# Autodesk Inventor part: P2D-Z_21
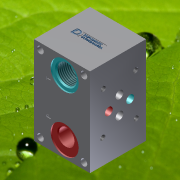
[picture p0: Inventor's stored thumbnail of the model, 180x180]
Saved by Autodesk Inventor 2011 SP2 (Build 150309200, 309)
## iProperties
Category: PARTsolutions
Company: DUPLOMATIC
Created: 2013-08
Part Number: P2D-Z_21
Catalog Web Link: www.cadenas.de
Description: P2D-*-Modular subplates
Vendor: DUPLOMATIC
Document SubType Name: Modeling
Designer: PARTuser1
Manufacturer: DUPLOMATIC
Density: 1 g/cm^3
PSOL_IDENT_0: {$CADENAS_DATA\23d-libs\duplomatic\05_subplates_and_manifolds\52000\p2d.prj},165 {VTYP=3D},{NB=15600
PSOL_IDENT_1: 25-06},{LINA=P2D-Z/21},{NN=P2D-*},{DATE=08.11.2012 07:04:15},{GEOMDATE=07.11.2012 00:00:00},{VERSION
PSOL_IDENT_2: =},{LINEID=10},{LINESUBID=-1},{WBVAR=VER,GU}  {NB=1560025-06},{LINA=P2D-Z/21},{KT=DUMMY},{CODE=15600
PSOL_IDENT_3: 25-06},{TIPO=P2D},{VER=Z},{SER=21},{GU=},{PORT=Rear ports},{LAG=P2D-Z/21},{VERS=4}
CNS_NT: Modular subplates
CNS_NB: 1560025-06
CNS_NBSYN: $CODE.$GU.
CNS_LINA: P2D-Z/21
CNS_CODE: 1560025-06
CNS_TIPO: P2D
CNS_VER: Z = arranged for the installation of an MZD
CNS_SER: 21
CNS_GU: NBR
CNS_PORT: Rear ports
CNS_LAG: P2D-Z/21
CNS_VERS: 4
SUPPLIER: DUPLOMATIC
ARTICLENO: 1560025-06
BOMINFO: P2D-Z/21
CREATOR: CADENAS GmbH
Title: P2D-Z/21
Author: Cadenas PARTsolutions
Comments: Modular subplates
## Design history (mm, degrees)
sketch "Sketch_1"
  geometry: L1 (-27, 27)-(-27, -27); L2 (-27, -27)-(27, -27); L3 (27, -27)-(27, 27); L4 (27, 27)-(-27, 27)
  constraints: 8 end point
extrude "Extrusion1" join sketch "Sketch_1" stored distance "d0" = 85; taper "d1" = 0 deg
sketch "Sketch_2"
  geometry: L1 (-27, -8)-(-27, -27); L2 (-27, -27)-(-40.5, -27); L3 (-40.5, -27)-(-40.5, -25.7); L4 (-40.5, -25.7)-(-37.477, -25.7); L5 (-37.477, -25.7)-(-36.316, -24.538); L6 (-36.316, -24.538)-(-36.316, -8); L7 (-36.316, -8)-(-27, -8); L8 (-27, -8)-(-27, -27)
  constraints: 16 end point
revolve "Revolution1" sketch "Sketch_2" stored, may be unused: angle "d2" = 360 deg
thread "Thread1" dims "d3" = 14.5, "d4" = 3.2
sketch "Sketch3"
  geometry: 1 further point
hole "Drilling 2" sketch "Sketch3" at (29.5, 17.5) diameter "d5" = 14.95; stored, may be unused: countersink angle "d9" = 90 deg, drill point angle "d11" = 0 deg; dims "d6" = 6, "d7" = 16.662, "d8" = 2, "d10" = 35
sketch "Sketch_30"
  geometry: L1 (27, -25.7)-(27, -27); L2 (27, -27)-(13.5, -27); L3 (13.5, -27)-(13.5, -25.7); L4 (13.5, -25.7)-(27, -25.7); L5 (27, -25.7)-(27, -27)
  constraints: 10 end point
revolve "Revolution2" sketch "Sketch_30" stored, may be unused: angle "d12" = 360 deg
sketch "Sketch5"
  geometry: 1 further point
hole "Drilling 4" sketch "Sketch5" at (0, 2) diameter "d13" = 14.95; stored, may be unused: countersink angle "d17" = 90 deg, drill point angle "d19" = 120 deg; dims "d14" = 6, "d15" = 16.662, "d16" = 2, "d18" = 17.88431
sketch "Sketch6"
  geometry: 1 further point
hole "Drilling 5" sketch "Sketch6" at (29.5, 67.5) diameter "d20" = 14.95; stored, may be unused: countersink angle "d24" = 90 deg, drill point angle "d26" = 120 deg; dims "d21" = 6, "d22" = 16.662, "d23" = 2, "d25" = 22.68431
sketch "Sketch7"
  geometry: 1 further point
hole "Drilling 6" sketch "Sketch7" at (6, -6) diameter "d27" = 6.3; stored, may be unused: countersink angle "d31" = 90 deg, drill point angle "d33" = 0 deg; dims "d28" = 6, "d29" = 6.7, "d30" = 2, "d32" = 54
pattern_linear "Rectangular Pattern1" dims "d36" = 42, "d39" = 73
sketch "Sketch8"
  geometry: 1 further point
hole "Drilling 7" sketch "Sketch8" at (42.5, 18.2) diameter "d40" = 7.5; stored, may be unused: countersink angle "d44" = 90 deg, drill point angle "d46" = 120 deg; dims "d41" = 6, "d42" = 4, "d43" = 2, "d45" = 25.83494
sketch "Sketch9"
  geometry: 1 further point
hole "Drilling 8" sketch "Sketch9" at (42.5, 38.8) diameter "d47" = 7.5; stored, may be unused: countersink angle "d51" = 90 deg, drill point angle "d53" = 120 deg; dims "d48" = 6, "d49" = 4, "d50" = 2, "d52" = 25.83494
sketch "Sketch10"
  geometry: 1 further point
hole "Drilling 9" sketch "Sketch10" at (33.7, 28.5) diameter "d54" = 7.5; stored, may be unused: countersink angle "d58" = 90 deg, drill point angle "d60" = 120 deg; dims "d55" = 6, "d56" = 4, "d57" = 2, "d59" = 42.83494
sketch "Sketch11"
  geometry: 1 further point
hole "Drilling 10" sketch "Sketch11" at (51.2, 28.5) diameter "d61" = 7.5; stored, may be unused: countersink angle "d65" = 90 deg, drill point angle "d67" = 120 deg; dims "d62" = 6, "d63" = 4, "d64" = 2, "d66" = 42.83494
sketch "Sketch12"
  geometry: 1 further point
hole "Drilling 11" sketch "Sketch12" at (21, 13.05) diameter "d68" = 4.134; stored, may be unused: countersink angle "d72" = 90 deg, drill point angle "d74" = 120 deg; dims "d69" = 10, "d70" = 5, "d71" = 2, "d73" = 11.80662
sketch "Sketch13"
  geometry: 1 further point
hole "Pattern 2_Drilling 11_3" sketch "Sketch13" at (61.5, 44.8) diameter "d75" = 4.134; stored, may be unused: countersink angle "d79" = 90 deg, drill point angle "d81" = 120 deg; dims "d76" = 10, "d77" = 5, "d78" = 2, "d80" = 11.80662
sketch "Sketch14"
  geometry: 1 further point
hole "Pattern 2_Drilling 11_2" sketch "Sketch14" at (21, 44.05) diameter "d82" = 4.134; stored, may be unused: countersink angle "d86" = 90 deg, drill point angle "d88" = 120 deg; dims "d83" = 10, "d84" = 5, "d85" = 2, "d87" = 11.80662
sketch "Sketch15"
  geometry: 1 further point
hole "Pattern 2_Drilling 11_1" sketch "Sketch15" at (61.5, 12.3) diameter "d89" = 4.134; stored, may be unused: countersink angle "d93" = 90 deg, drill point angle "d95" = 120 deg; dims "d90" = 10, "d91" = 5, "d92" = 2, "d94" = 11.80662
sketch "Sketch_14"
  geometry: L1 (-5.5, -16.5)-(-27, -16.5); L2 (-27, -16.5)-(-27, -4.5); L3 (-27, -4.5)-(-26, -4.5); L4 (-26, -4.5)-(-26, -8.169); L5 (-26, -8.169)-(-25.144, -9.025); L6 (-25.144, -9.025)-(-9.5, -9.025); L7 (-9.5, -9.025)-(-5.5, -16.5); L8 (-5.5, -16.5)-(-27, -16.5)
  constraints: 16 end point
revolve "Revolution3" sketch "Sketch_14" stored, may be unused: angle "d96" = 360 deg
thread "Thread2" dims "d97" = 12.144, "d98" = 0
sketch "Sketch_15"
  geometry: L1 (1.5, 16.5)-(-27, 16.5); L2 (-27, 16.5)-(-27, 28.5); L3 (-27, 28.5)-(-26, 28.5); L4 (-26, 28.5)-(-26, 24.831); L5 (-26, 24.831)-(-25.144, 23.975); L6 (-25.144, 23.975)-(-2.816, 23.975); L7 (-2.816, 23.975)-(1.5, 16.5); L8 (1.5, 16.5)-(-27, 16.5)
  constraints: 16 end point
revolve "Revolution4" sketch "Sketch_15" stored, may be unused: angle "d99" = 360 deg
thread "Thread3" dims "d100" = 12.144, "d101" = 0
sketch "Sketch_16"
  geometry: L1 (-9.422, -3.5)-(12.117, -3.5); L2 (12.117, 3)-(-9.422, 3); L3 (11.496, -2.508)-(11.868, -2.508); L4 (11.868, -2.508)-(12.052, -2.061); L5 (12.052, -2.061)-(12.833, -2.061); L6 (12.833, -2.061)-(13.012, -2.508); L7 (13.012, -2.508)-(13.387, -2.508); L8 (13.387, -2.508)-(12.654, -0.699); L9 (12.654, -0.699)-(12.245, -0.699); L10 (12.245, -0.699)-(11.496, -2.508); L11 (10.766, -2.508)-(11.358, -2.508); L12 (11.358, -2.508)-(11.358, -2.237); L13 (11.358, -2.237)-(10.812, -2.237); L14 (10.794, -0.97)-(11.358, -0.97); L15 (11.358, -0.97)-(11.358, -0.699); L16 (11.358, -0.699)-(10.764, -0.699); L17 (9.283, -0.973)-(9.614, -0.973); L18 (9.614, -0.973)-(9.614, -0.699); L19 (9.614, -0.699)-(9.283, -0.699); L20 (9.283, -0.699)-(9.283, -0.973); L21 (9.283, -2.508)-(9.614, -2.508); L22 (9.614, -2.508)-(9.614, -1.164); L23 (9.614, -1.164)-(9.283, -1.164); L24 (9.283, -1.164)-(9.283, -2.508); L25 (9.507, 0.199)-(10.098, 0.199); L26 (10.098, 0.199)-(10.098, 0.47); L27 (10.098, 0.47)-(9.553, 0.47); L28 (9.534, 1.737)-(10.098, 1.737); L29 (10.098, 1.737)-(10.098, 2.008); L30 (10.098, 2.008)-(9.504, 2.008); L31 (8.023, 0.199)-(8.354, 0.199); L32 (8.354, 0.199)-(8.354, 1.545); L33 (8.354, 1.545)-(8.023, 1.545); L34 (8.023, 1.545)-(8.023, 0.199); L35 (8.023, 1.736)-(8.354, 1.736); L36 (8.354, 1.736)-(8.354, 2.008); L37 (8.354, 2.008)-(8.023, 2.008); L38 (8.023, 2.008)-(8.023, 1.736); L39 (6.885, -2.508)-(7.205, -2.508); L40 (7.205, -2.508)-(7.205, -1.052); L41 (7.205, -1.052)-(7.726, -2.508); L42 (7.726, -2.508)-(8.062, -2.508); L43 (8.062, -2.508)-(8.583, -1.052); L44 (8.583, -1.052)-(8.583, -2.508); L45 (8.583, -2.508)-(8.903, -2.508); L46 (8.903, -2.508)-(8.903, -0.699); L47 (8.903, -0.699)-(8.415, -0.699); L48 (8.415, -0.699)-(7.902, -2.145); L49 (7.902, -2.145)-(7.373, -0.699); L50 (7.373, -0.699)-(6.885, -0.699); L51 (6.885, -0.699)-(6.885, -2.508); L52 (6.274, 1.737)-(6.879, 1.737); L53 (6.879, 1.737)-(6.879, 0.199); L54 (6.879, 0.199)-(7.21, 0.199); L55 (7.21, 0.199)-(7.21, 1.737); L56 (7.21, 1.737)-(7.823, 1.737); L57 (7.823, 1.737)-(7.823, 2.008); L58 (7.823, 2.008)-(6.274, 2.008); L59 (6.274, 2.008)-(6.274, 1.737); L60 (4.799, -2.508)-(5.17, -2.508); L61 (5.17, -2.508)-(5.355, -2.061); L62 (5.355, -2.061)-(6.136, -2.061); L63 (6.136, -2.061)-(6.315, -2.508); L64 (6.315, -2.508)-(6.689, -2.508)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; A1 r 3.25 centre (12.117, -0.25) between (12.117, -3.5) and (12.117, 3); A2 r 3.9 centre (-11.578, -0.25) between (-9.422, -3.5) and (-9.422, 3); A3 r 1.348 centre (11.244, -1.62) between (10.001, -1.096) and (9.947, -1.989); A4 r 0.901 centre (10.807, -1.719) between (9.947, -1.989) and (10.132, -2.316); A5 r 0.709 centre (10.607, -1.789) between (10.132, -2.316) and (10.476, -2.487); A6 r 1.885 centre (10.761, -0.623) between (10.476, -2.487) and (10.766, -2.508); A7 r 1.097 centre (10.812, -1.14) between (10.555, -2.206) and (10.812, -2.237); A8 r 0.418 centre (10.696, -1.813) between (10.422, -2.129) and (10.555, -2.206); A9 r 0.377 centre (10.667, -1.842) between (10.295, -1.905) and (10.422, -2.129); A10 r 1.462 centre (11.722, -1.588) between (10.274, -1.387) and (10.295, -1.905); A11 r 0.615 centre (10.885, -1.459) between (10.376, -1.114) and (10.274, -1.387); A12 r 0.426 centre (10.688, -1.404) between (10.597, -0.987) and (10.376, -1.114); A13 r 2.262 centre (10.892, -3.23) between (10.794, -0.97) and (10.597, -0.987); A14 r 1.706 centre (10.766, -2.405) between (10.764, -0.699) and (10.504, -0.719); A15 r 0.6 centre (10.568, -1.316) between (10.504, -0.719) and (10.254, -0.805); A16 r 0.839 centre (10.745, -1.485) between (10.254, -0.805) and (10.001, -1.096); A17 r 1.348 centre (9.984, 1.087) between (8.742, 1.611) and (8.688, 0.718); A18 r 0.901 centre (9.547, 0.989) between (8.688, 0.718) and (8.872, 0.392); A19 r 0.709 centre (9.348, 0.918) between (8.872, 0.392) and (9.217, 0.221); A20 r 1.887 centre (9.502, 2.086) between (9.217, 0.221) and (9.507, 0.199); A21 r 1.097 centre (9.553, 1.568) between (9.295, 0.501) and (9.553, 0.47); A22 r 0.418 centre (9.437, 0.894) between (9.163, 0.579) and (9.295, 0.501); A23 r 0.377 centre (9.407, 0.866) between (9.035, 0.803) and (9.163, 0.579); A24 r 1.462 centre (10.463, 1.119) between (9.015, 1.32) and (9.035, 0.803); A25 r 0.615 centre (9.625, 1.248) between (9.116, 1.593) and (9.015, 1.32); A26 r 0.426 centre (9.429, 1.304) between (9.338, 1.72) and (9.116, 1.593); A27 r 2.262 centre (9.632, -0.522) between (9.534, 1.737) and (9.338, 1.72); A28 r 1.706 centre (9.507, 0.303) between (9.504, 2.008) and (9.245, 1.988); A29 r 0.6 centre (9.309, 1.392) between (9.245, 1.988) and (8.994, 1.903); A30 r 0.839 centre (9.486, 1.222) between (8.994, 1.903) and (8.742, 1.611); A31 r 3.457 centre (1.169, 0.949) between (1.161, -2.508) and (1.422, -2.499); A32 r 0.716 centre (1.36, -1.785) between (1.422, -2.499) and (1.742, -2.392); A33 r 0.46 centre (1.485, -2.01) between (1.742, -2.392) and (1.893, -2.222); A34 r 1.26 centre (0.792, -1.611) between (1.893, -2.222) and (2.051, -1.57); A35 r 1.248 centre (0.803, -1.605) between (2.051, -1.57) and (1.847, -0.921); A36 r 0.492 centre (1.455, -1.219) between (1.847, -0.921) and (1.514, -0.73); A37 r 3.717 centre (1.02, -4.414) between (1.514, -0.73) and (1.147, -0.699); A38 r 1.116 centre (1.17, -2.087) between (1.297, -0.978) and (1.166, -0.97); A39 r 0.454 centre (1.234, -1.427) between (1.541, -1.092) and (1.297, -0.978); A40 r 0.992 centre (0.698, -1.615) between (1.689, -1.583) and (1.541, -1.092); A41 r 1.21 centre (0.48, -1.568) between (1.576, -2.08) and (1.689, -1.583); A42 r 0.416 centre (1.256, -1.815) between (1.361, -2.217) and (1.576, -2.08); A43 r 1.083 centre (1.153, -1.155) between (1.177, -2.237) and (1.361, -2.217); A44 r 1.301 centre (1.624, 1.101) between (0.444, 1.651) and (0.402, 0.652); A45 r 0.845 centre (1.2, 0.931) between (0.402, 0.652) and (0.488, 0.476); A46 r 0.529 centre (0.925, 0.774) between (0.488, 0.476) and (0.682, 0.304); A47 r 1.143 centre (1.2, 1.323) between (0.682, 0.304) and (1.799, 0.35); A48 r 0.411 centre (1.586, 0.702) between (1.799, 0.35) and (1.967, 0.547); A49 r 1.422 centre (0.665, 1.119) between (1.967, 0.547) and (2.016, 1.563); A50 r 0.471 centre (1.562, 1.437) between (2.016, 1.563) and (1.934, 1.726); A51 r 0.532 centre (1.489, 1.434) between (1.934, 1.726) and (1.743, 1.902); A52 r 1.019 centre (1.252, 1.009) between (1.743, 1.902) and (1.226, 2.027); A53 r 1.388 centre (1.257, 0.639) between (1.226, 2.027) and (0.721, 1.92); A54 r 0.675 centre (1.033, 1.322) between (0.721, 1.92) and (0.444, 1.651); A55 r 1.477 centre (0.539, 0.931) between (-0.938, 0.953) and (-0.893, 0.566); A56 r 0.405 centre (-0.502, 0.67) between (-0.893, 0.566) and (-0.773, 0.37); A57 r 0.708 centre (-0.307, 0.904) between (-0.773, 0.37) and (-0.551, 0.239); A58 r 1.672 centre (-0.189, 1.871) between (-0.551, 0.239) and (-0.173, 0.199); A59 r 1.417 centre (-0.096, 1.888) between (-0.383, 0.499) and (-0.125, 0.47); A60 r 0.235 centre (-0.347, 0.732) between (-0.521, 0.573) and (-0.383, 0.499); A61 r 0.279 centre (-0.312, 0.758) between (-0.581, 0.687) and (-0.521, 0.573); A62 r 1.466 centre (0.858, 0.962) between (-0.608, 0.972) and (-0.581, 0.687); A63 r 1.301 centre (-0.326, -1.607) between (-1.506, -1.057) and (-1.548, -2.056); A64 r 0.845 centre (-0.75, -1.776) between (-1.548, -2.056) and (-1.462, -2.232)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
  constraints: 322 end point, 278 point on circle, 139 centre point
extrude "Extrusion2" cut sketch "Sketch_16" distance "d102" = 0.5; taper "d103" = 0 deg
sketch "Sketch_17"
  geometry: A1 r 1.562 centre (-4.673, -1.589) between (-6.223, -1.401) and (-6.199, -1.919); A2 r 0.482 centre (-5.731, -1.806) between (-6.199, -1.919) and (-6.075, -2.144); A3 r 0.667 centre (-5.693, -1.597) between (-6.075, -2.144) and (-5.712, -2.264); A4 r 0.666 centre (-5.728, -1.598) between (-5.712, -2.264) and (-5.354, -2.149); A5 r 0.436 centre (-5.654, -1.833) between (-5.354, -2.149) and (-5.228, -1.925); A6 r 1.467 centre (-6.66, -1.606) between (-5.228, -1.925) and (-5.23, -1.279); A7 r 0.378 centre (-5.602, -1.345) between (-5.23, -1.279) and (-5.358, -1.056); A8 r 0.602 centre (-5.71, -1.545) between (-5.358, -1.056) and (-6.083, -1.072); A9 r 0.296 centre (-5.89, -1.297) between (-6.083, -1.072) and (-6.16, -1.176); A10 r 0.63 centre (-5.596, -1.457) between (-6.16, -1.176) and (-6.223, -1.401)
  constraints: 20 point on circle, 10 centre point
extrude "Extrusion3" cut sketch "Sketch_17" distance "d104" = 0.5; taper "d105" = 0 deg
sketch "Sketch_18"
  geometry: A1 r 1.562 centre (2.246, 1.119) between (0.696, 1.306) and (0.72, 0.788); A2 r 0.482 centre (1.189, 0.901) between (0.72, 0.788) and (0.845, 0.563); A3 r 0.667 centre (1.227, 1.11) between (0.845, 0.563) and (1.207, 0.443); A4 r 0.666 centre (1.191, 1.109) between (1.207, 0.443) and (1.565, 0.558); A5 r 0.436 centre (1.266, 0.875) between (1.565, 0.558) and (1.692, 0.782); A6 r 1.467 centre (0.259, 1.101) between (1.692, 0.782) and (1.69, 1.428); A7 r 0.378 centre (1.318, 1.362) between (1.69, 1.428) and (1.561, 1.651); A8 r 0.602 centre (1.21, 1.162) between (1.561, 1.651) and (0.837, 1.635); A9 r 0.296 centre (1.03, 1.411) between (0.837, 1.635) and (0.759, 1.531); A10 r 0.63 centre (1.323, 1.251) between (0.759, 1.531) and (0.696, 1.306)
  constraints: 20 point on circle, 10 centre point
extrude "Extrusion4" cut sketch "Sketch_18" distance "d106" = 0.5; taper "d107" = 0 deg
sketch "Sketch_19"
  geometry: A1 r 1.562 centre (0.296, -1.589) between (-1.254, -1.401) and (-1.23, -1.919); A2 r 0.482 centre (-0.761, -1.806) between (-1.23, -1.919) and (-1.105, -2.144); A3 r 0.667 centre (-0.723, -1.597) between (-1.105, -2.144) and (-0.743, -2.264); A4 r 0.666 centre (-0.759, -1.598) between (-0.743, -2.264) and (-0.385, -2.149); A5 r 0.436 centre (-0.684, -1.833) between (-0.385, -2.149) and (-0.258, -1.925); A6 r 1.467 centre (-1.691, -1.606) between (-0.258, -1.925) and (-0.26, -1.279); A7 r 0.378 centre (-0.632, -1.345) between (-0.26, -1.279) and (-0.389, -1.056); A8 r 0.602 centre (-0.74, -1.545) between (-0.389, -1.056) and (-1.113, -1.072); A9 r 0.296 centre (-0.92, -1.297) between (-1.113, -1.072) and (-1.191, -1.176); A10 r 0.63 centre (-0.627, -1.457) between (-1.191, -1.176) and (-1.254, -1.401)
  constraints: 20 point on circle, 10 centre point
extrude "Extrusion5" cut sketch "Sketch_19" distance "d108" = 0.5; taper "d109" = 0 deg
sketch "Sketch_20"
  geometry: L1 (5.23, 0.918)-(5.834, 0.918); L2 (5.834, 0.918)-(5.536, 1.694); L3 (5.536, 1.694)-(5.23, 0.918)
  constraints: 6 end point
extrude "Extrusion6" cut sketch "Sketch_20" distance "d110" = 0.5; taper "d111" = 0 deg
sketch "Sketch_21"
  geometry: L1 (5.442, -1.79)-(6.047, -1.79); L2 (6.047, -1.79)-(5.748, -1.014); L3 (5.748, -1.014)-(5.442, -1.79)
  constraints: 6 end point
extrude "Extrusion7" cut sketch "Sketch_21" distance "d112" = 0.5; taper "d113" = 0 deg
sketch "Sketch_22"
  geometry: L1 (12.139, -1.79)-(12.744, -1.79); L2 (12.744, -1.79)-(12.445, -1.014); L3 (12.445, -1.014)-(12.139, -1.79)
  constraints: 6 end point
extrude "Extrusion8" cut sketch "Sketch_22" distance "d114" = 0.5; taper "d115" = 0 deg
sketch "Sketch_23"
  geometry: L1 (-27, -27)-(27, -27); L2 (27, -27)-(27, 27); L3 (27, 27)-(-27, 27); L4 (-27, 27)-(-27, -27); L5 (-9.422, -3.5)-(12.117, -3.5); L6 (12.117, 3)-(-9.422, 3); A1 r 3.25 centre (12.117, -0.25) between (12.117, -3.5) and (12.117, 3); A2 r 3.9 centre (-11.578, -0.25) between (-9.422, -3.5) and (-9.422, 3)
  constraints: 12 end point, 4 point on circle, 2 centre point
extrude "Extrusion9" cut sketch "Sketch_23" distance "d116" = 0.5; taper "d117" = 0 deg
sketch "Sketch_24"
  geometry: L1 (-27, -27)-(27, -27); L2 (27, -27)-(27, 27); L3 (27, 27)-(-27, 27); L4 (-27, 27)-(-27, -27); L5 (-9.422, -3.5)-(12.117, -3.5); L6 (12.117, 3)-(-9.422, 3); A1 r 3.25 centre (12.117, -0.25) between (12.117, -3.5) and (12.117, 3); A2 r 3.9 centre (-11.578, -0.25) between (-9.422, -3.5) and (-9.422, 3)
  constraints: 12 end point, 4 point on circle, 2 centre point
extrude "Extrusion10" join sketch "Sketch_24" distance "d118" = 0.5; taper "d119" = 0 deg
sketch "Sketch_25"
  geometry: L1 (-15.36, 1.109)-(-15.36, -3.5); L2 (-15.36, -3.5)-(-12.11, -3.5); L3 (-12.11, 3)-(-14.835, 3); L4 (-14.835, 3)-(-15.36, 1.7); L5 (-15.36, 1.7)-(-12.11, 1.7); L6 (-12.11, -2.2)-(-14.06, -2.2); L7 (-14.06, -2.2)-(-12.723, 1.109); L8 (-12.723, 1.109)-(-15.36, 1.109); A1 r 3.25 centre (-12.11, -0.25) between (-12.11, -3.5) and (-12.11, 3); A2 r 1.95 centre (-12.11, -0.25) between (-12.11, -2.2) and (-12.11, 1.7)
  constraints: 16 end point, 4 point on circle, 2 centre point
extrude "Extrusion11" cut sketch "Sketch_25" distance "d120" = 0.5; taper "d121" = 0 deg
sketch "Sketch_26"
  geometry: L1 (9.125, 17)-(10.5, 17); L2 (10.5, 17)-(10.5, 21); L3 (10.5, 21)-(9.125, 21); L4 (9.125, 17.5)-(10, 17.5); L5 (10, 17.5)-(10, 18.75); L6 (10, 18.75)-(9.125, 18.75); L7 (9.125, 19.25)-(10, 19.25); L8 (10, 19.25)-(10, 20.5); L9 (10, 20.5)-(9.125, 20.5); A1 r 1.125 centre (9.125, 19.875) between (9.125, 21) and (8.418, 19); A2 r 1.125 centre (9.125, 18.125) between (8.418, 19) and (9.125, 17); A3 r 0.625 centre (9.125, 18.125) between (9.125, 18.75) and (9.125, 17.5); A4 r 0.625 centre (9.125, 19.875) between (9.125, 20.5) and (9.125, 19.25)
  constraints: 18 end point, 8 point on circle, 4 centre point
extrude "Extrusion12" cut sketch "Sketch_26" distance "d122" = 0.5; taper "d123" = 0 deg
sketch "Sketch_27"
  geometry: L1 (-10.5, 17)-(-9.985, 17); L2 (-9.985, 17)-(-9.61, 18.5); L3 (-9.61, 18.5)-(-8.89, 18.5); L4 (-8.89, 18.5)-(-8.515, 17); L5 (-8.515, 17)-(-8, 17); L6 (-8, 17)-(-9, 21); L7 (-9, 21)-(-9.5, 21); L8 (-9.5, 21)-(-10.5, 17); L9 (-9.485, 19)-(-9.015, 19); L10 (-9.015, 19)-(-9.25, 19.938); L11 (-9.25, 19.938)-(-9.485, 19)
  constraints: 22 end point
extrude "Extrusion13" cut sketch "Sketch_27" distance "d124" = 0.5; taper "d125" = 0 deg
sketch "Sketch_28"
  geometry: L1 (-15, 16.25)-(-15, 14.875); L2 (-12.75, 14.875)-(-12.75, 15.75); L3 (-12.75, 15.75)-(-11, 15.75); L4 (-11, 15.75)-(-11, 16.25); L5 (-11, 16.25)-(-15, 16.25); L6 (-13.25, 14.875)-(-13.25, 15.75); L7 (-13.25, 15.75)-(-14.5, 15.75); L8 (-14.5, 15.75)-(-14.5, 14.875); A1 r 1.125 centre (-13.875, 14.875) between (-15, 14.875) and (-12.75, 14.875); A2 r 0.625 centre (-13.875, 14.875) between (-14.5, 14.875) and (-13.25, 14.875)
  constraints: 16 end point, 4 point on circle, 2 centre point
extrude "Extrusion14" cut sketch "Sketch_28" distance "d126" = 0.5; taper "d127" = 0 deg
sketch "Sketch_29"
  geometry: L1 (-15, -15)-(-15, -17.5); L2 (-15, -17.5)-(-14.5, -17.5); L3 (-14.5, -17.5)-(-14.5, -16.5); L4 (-14.5, -16.5)-(-11, -16.5); L5 (-11, -16.5)-(-11, -16); L6 (-11, -16)-(-14.5, -16); L7 (-14.5, -16)-(-14.5, -15); L8 (-14.5, -15)-(-15, -15)
  constraints: 16 end point
extrude "Extrusion15" cut sketch "Sketch_29" distance "d128" = 0.5; taper "d129" = 0 deg
body "Solid1"
